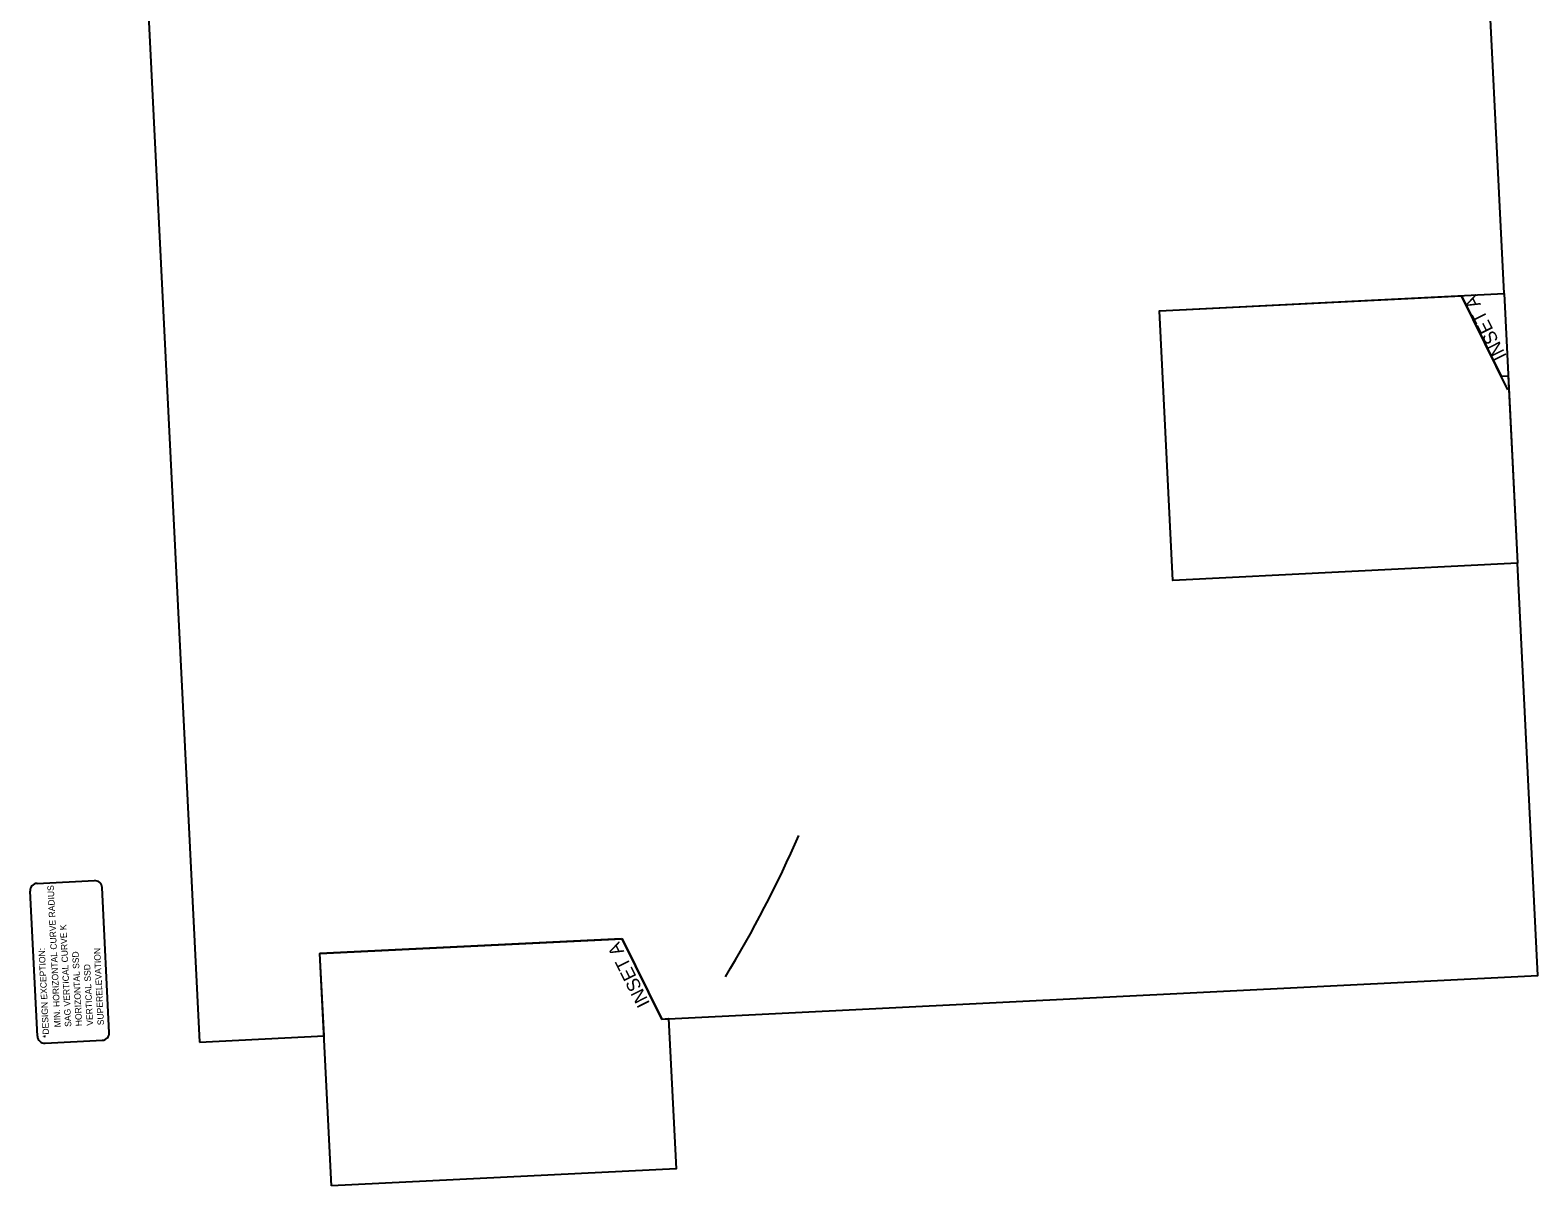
# Model space of a CAD drawing. Extents: x 1807150 to 1808331, y 913657 to 915467.
# Drawn here: x 1807150 to 1808331, y 913657 to 914562 of the extents above; entities that cross this region are included whole.
import ezdxf

# ---------------------------------------------------------------- set-up
doc = ezdxf.new("R2010")
doc.units = 0
for name, color, linetype in [('Exist Plan Preparation Watershed Blue', 7, 'Continuous'), ('Old_Level_18', 7, 'Continuous'), ('Old_Level_38', 7, 'Continuous'), ('Prop Boundary Buffer Zone 2', 7, 'Continuous'), ('Prop Drainage Structure Plot Symbol 50 Scale', 7, 'Continuous'), ('Scratch_Level_2', 7, 'Continuous')]:
    doc.layers.add(name, color=color, linetype=linetype)

msp = doc.modelspace()

# ---------------------------------------------------------------- linework, layer by layer
at = {"layer": 'Exist Plan Preparation Watershed Blue'}
for p, q in [((1808307.9, 914280.6), (1808271.6, 914354.2)), ((1807613.3, 913850.7), (1807377.1, 913839)), ((1807644.9, 913787.8), (1807613.9, 913850.7))]:
    msp.add_line(p, q, dxfattribs=at)
at = {"layer": 'Old_Level_18'}
for p, q in [((1807155.5, 913894), (1807200.4, 913896.2)), ((1807155.7, 913774.4), (1807150, 913888)), ((1807212, 913777.1), (1807206.4, 913890.8)), ((1807161.7, 913768.9), (1807206.6, 913771.2))]:
    msp.add_line(p, q, dxfattribs=at)
msp.add_lwpolyline([(1808304.9, 914355.9), (1808315.3, 914144.7), (1808045.3, 914131.3), (1808034.8, 914342.5)], close=True, dxfattribs=at)
msp.add_lwpolyline([(1808304.9, 914355.9), (1808315.3, 914144.7), (1808045.3, 914131.3), (1808034.8, 914342.5)], close=True, dxfattribs=at)
for centre, start, end in [((1807155.7, 913888.3), 92.8422, 182.8422), ((1807200.7, 913890.5), 2.8422, 92.8422), ((1807206.3, 913776.9), 272.8422, 2.8422), ((1807161.4, 913774.6), 182.8422, 272.8422)]:
    msp.add_arc(centre, 5.71, start, end, dxfattribs=at)
at = {"layer": 'Prop Boundary Buffer Zone 2'}
msp.add_arc((1806877.3, 914316.4), 956, 328.7751, 336.2667, dxfattribs=at)
at = {"layer": 'Scratch_Level_2'}
for points in [[(1807282.7, 913769.8), (1807380.3, 913774.7), (1807377.1, 913839), (1807613.9, 913850.7), (1807644.9, 913787.8), (1808331.4, 913821.9), (1808315.3, 914144.7), (1808045.3, 914131.3), (1808034.8, 914342.5), (1808304.9, 914355.9), (1808257.3, 915314.8), (1807444, 915192.5), (1807449.6, 915079.7), (1807218.2, 915068.2)], [(1808045.3, 914131.3), (1808034.8, 914342.5), (1808271.6, 914354.2), (1808302.6, 914291.3), (1808308.1, 914291.6), (1808315.3, 914144.7)], [(1807386.1, 913657.2), (1807377.1, 913839), (1807613.9, 913850.7), (1807644.9, 913787.8), (1807650.3, 913788.1), (1807656.2, 913670.6)]]:
    msp.add_lwpolyline(points, close=True, dxfattribs=at)

# ---------------------------------------------------------------- texts
at = {"layer": 'Old_Level_38'}
for s, p in [('MIN. HORIZONTAL CURVE RADIUS', (1807174, 913781.4)), ('SAG VERTICAL CURVE K', (1807182.3, 913781.8)), ('*DESIGN EXCEPTION: ', (1807165, 913773.1)), ('HORIZONTAL SSD', (1807190.8, 913782.3)), ('SUPERELEVATION', (1807207.9, 913783.1)), ('VERTICAL SSD', (1807199.4, 913782.7))]:
    msp.add_text(s, height=5, rotation=92.8372, dxfattribs=at).set_placement(p)
at = {"layer": 'Prop Drainage Structure Plot Symbol 50 Scale'}
for p in [(1808307.2, 914306.9), (1807635.9, 913800.1)]:
    msp.add_text('INSET A', height=10.5, rotation=116.672, dxfattribs=at).set_placement(p)

doc.saveas('drawing.dxf')
